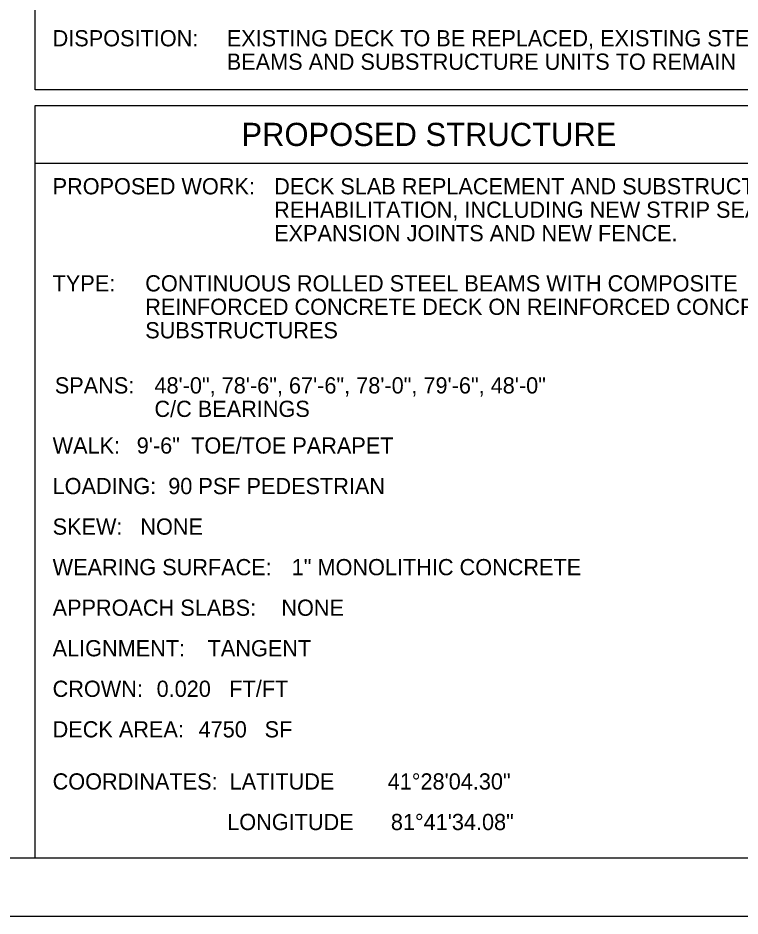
# Model space of a CAD drawing. Extents: x 39.5 to 77.6, y 9.5 to 31.5.
# Drawn here: x 64.08 to 70.32, y 9.5 to 17.25 of the extents above; entities that cross this region are included whole.
import ezdxf

# ---------------------------------------------------------------- set-up
doc = ezdxf.new("R2010")
doc.units = 0
for name, color, linetype in [('SH_Border', 7, 'Continuous'), ('SH_Cut_Line', 7, 'Continuous'), ('SH_Data', 7, 'Continuous')]:
    doc.layers.add(name, color=color, linetype=linetype)

msp = doc.modelspace()

# ---------------------------------------------------------------- linework, layer by layer
at = {"layer": 'SH_Border'}
msp.add_lwpolyline([(40.9807, 30.9995), (72.9807, 30.9995), (72.9807, 9.9995), (40.9807, 9.9995)], close=True, dxfattribs=at)
at = {"layer": 'SH_Cut_Line'}
msp.add_lwpolyline([(39.4807, 9.4995), (73.4807, 9.4995), (73.4807, 31.4995), (39.4807, 31.4995)], close=True, dxfattribs=at)
at = {"layer": 'SH_Data'}
msp.add_line((71.4807, 15.997), (64.2307, 15.997), dxfattribs=at)
for points in [[(64.2307, 22.247), (71.4807, 22.247), (71.4807, 16.6327), (64.2307, 16.6327)], [(64.2307, 16.497), (71.4807, 16.497), (71.4807, 9.9995), (64.2307, 9.9995)]]:
    msp.add_lwpolyline(points, close=True, dxfattribs=at)

# ---------------------------------------------------------------- texts
for s, height, p in [('DISPOSITION:', 0.14, (64.3807, 17.0072)), ('EXISTING DECK TO BE REPLACED, EXISTING STEEL ', 0.14, (65.8849, 17.0072)), ('BEAMS AND SUBSTRUCTURE UNITS TO REMAIN ', 0.14, (65.8849, 16.8047)), ('PROPOSED STRUCTURE', 0.2, (66.0117, 16.147)), ('PROPOSED WORK:', 0.14, (64.3807, 15.7295)), ('DECK SLAB REPLACEMENT AND SUBSTRUCTURE', 0.14, (66.2942, 15.7295)), ('REHABILITATION, INCLUDING NEW STRIP SEAL', 0.14, (66.2942, 15.527)), ('EXPANSION JOINTS AND NEW FENCE.', 0.14, (66.2942, 15.3245)), ('TYPE:', 0.14, (64.3807, 14.8914)), ('CONTINUOUS ROLLED STEEL BEAMS WITH COMPOSITE ', 0.14, (65.1807, 14.8914)), ('REINFORCED CONCRETE DECK ON REINFORCED CONCRETE ', 0.14, (65.1807, 14.6889)), ('SUBSTRUCTURES', 0.14, (65.1807, 14.4864)), ('SPANS:', 0.14, (64.3995, 14.0105)), ('48\'-0", 78\'-6", 67\'-6", 78\'-0", 79\'-6", 48\'-0" ', 0.14, (65.2603, 14.0105)), ('C/C BEARINGS', 0.14, (65.2603, 13.808)), ('WALK:', 0.14, (64.3807, 13.4914)), ('9\'-6"', 0.14, (65.1072, 13.4914)), ('TOE/TOE PARAPET', 0.14, (65.5776, 13.4914)), ('LOADING:  90 PSF PEDESTRIAN', 0.14, (64.3807, 13.1414)), ('SKEW:', 0.14, (64.3807, 12.7914)), ('NONE', 0.14, (65.1385, 12.7914)), ('WEARING SURFACE:', 0.14, (64.3807, 12.4414)), ('1" MONOLITHIC CONCRETE', 0.14, (66.4461, 12.4414)), ('APPROACH SLABS:', 0.14, (64.3807, 12.0914)), ('NONE', 0.14, (66.3568, 12.0914)), ('ALIGNMENT:', 0.14, (64.3807, 11.7414)), ('TANGENT', 0.14, (65.7195, 11.7414)), ('CROWN:', 0.14, (64.3807, 11.3914)), ('0.020', 0.14, (65.279, 11.3914)), ('FT/FT', 0.14, (65.9069, 11.3914)), ('DECK AREA:', 0.14, (64.3807, 11.0414)), ('4750', 0.14, (65.6418, 11.0414)), ('SF', 0.14, (66.2121, 11.0414)), ('COORDINATES:  LATITUDE', 0.14, (64.3807, 10.5914)), ('41°28\'04.30"', 0.14, (67.2752, 10.5914)), ('                             LONGITUDE', 0.14, (64.3807, 10.2414)), ('81°41\'34.08"', 0.14, (67.3026, 10.2414))]:
    msp.add_text(s, height=height, dxfattribs=at).set_placement(p)

doc.saveas('drawing.dxf')
